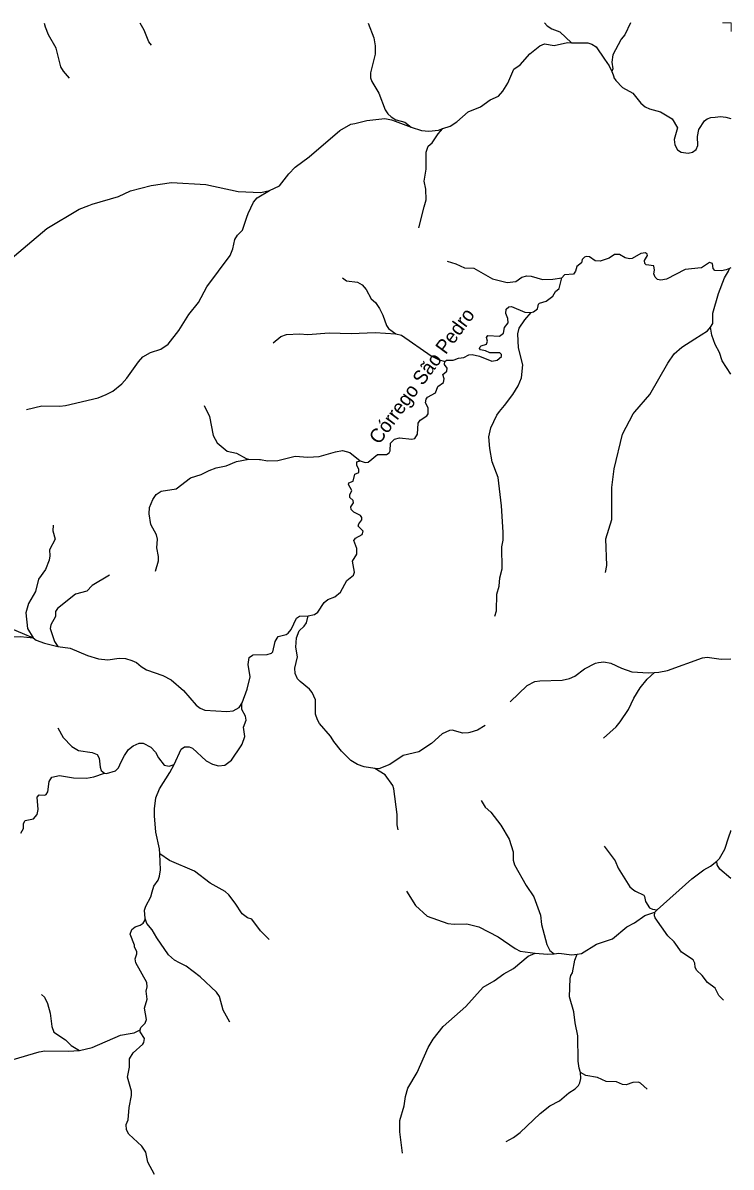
# Model space of a CAD drawing. Extents: x 473.9 to 500, y 7733.1 to 7760.8.
# Drawn here: x 494.97 to 500, y 7752.7 to 7760.82 of the extents above; entities that cross this region are included whole.
import ezdxf
from ezdxf.enums import TextEntityAlignment as Align

# ---------------------------------------------------------------- set-up
doc = ezdxf.new("R2010")
doc.units = 0
doc.header["$LTSCALE"] = 0.032
doc.layers.add('61', color=7, linetype='Continuous')
doc.layers.add('63', color=7, linetype='Continuous', lineweight=13)
doc.layers.add('7', color=7, linetype='Continuous', lineweight=25)

msp = doc.modelspace()

# ---------------------------------------------------------------- linework, layer by layer
at = {"layer": '63'}
msp.add_lwpolyline([(500.0013, 7760.7626), (500.0013, 7760.8242), (499.9406, 7760.8242)], dxfattribs=at)
at = {"layer": '7'}
for p, q in [((500, 7759.0846), (499.9899, 7759.0804)), ((499.4603, 7754.5076), (499.4762, 7754.5246))]:
    msp.add_line(p, q, dxfattribs=at)
for points in [[(495.3045, 7760.4309), (495.2616, 7760.4807), (495.2428, 7760.5119), (495.2083, 7760.6451), (495.1558, 7760.7389), (495.1323, 7760.7939), (495.1263, 7760.8213)], [(495.8869, 7760.6653), (495.8662, 7760.6904), (495.8343, 7760.7738), (495.805, 7760.8218)], [(497.424, 7760.8231), (497.4643, 7760.7172), (497.4745, 7760.6614), (497.4743, 7760.6021), (497.4408, 7760.4688), (497.4415, 7760.4332), (497.4494, 7760.4075), (497.4994, 7760.3251), (497.5462, 7760.2074), (497.5644, 7760.1777), (497.5869, 7760.1563), (497.6212, 7760.1369), (497.6228, 7760.1365), (497.6842, 7760.1198), (497.7308, 7760.0829)], [(498.6761, 7760.824), (498.6951, 7760.8029), (498.728, 7760.7816), (498.7846, 7760.7613), (498.8671, 7760.6826)], [(499.2881, 7760.8245), (499.2471, 7760.7408), (499.2215, 7760.7085), (499.2189, 7760.7052), (499.1624, 7760.5987), (499.155, 7760.5457), (499.1626, 7760.499), (499.1544, 7760.4786)], [(497.9549, 7760.0736), (498.0071, 7760.0907), (498.0539, 7760.1215), (498.134, 7760.1935), (498.2227, 7760.229), (498.2896, 7760.2775), (498.3496, 7760.3029), (498.3806, 7760.3385), (498.416, 7760.3965), (498.4581, 7760.4963), (498.5037, 7760.5276), (498.5726, 7760.6057), (498.6423, 7760.6614), (498.677, 7760.6758), (498.744, 7760.6646), (498.8403, 7760.6854), (498.8671, 7760.6826)], [(498.8671, 7760.6826), (498.9834, 7760.6823), (499.0125, 7760.6741), (499.0441, 7760.6535), (499.1035, 7760.5671), (499.1366, 7760.5191), (499.1544, 7760.4786)], [(499.1544, 7760.4786), (499.1696, 7760.4439), (499.1664, 7760.4399), (499.1823, 7760.4152), (499.2292, 7760.365), (499.3027, 7760.3244), (499.3604, 7760.2548), (499.3912, 7760.2278), (499.4227, 7760.2136), (499.5007, 7760.1926), (499.5819, 7760.1427), (499.6198, 7760.0789), (499.5976, 7759.9954), (499.602, 7759.9571), (499.6205, 7759.9216), (499.6476, 7759.9066), (499.6972, 7759.8981), (499.7261, 7759.9063), (499.7525, 7759.9251), (499.7652, 7759.9537), (499.7619, 7760.0179), (499.7713, 7760.0666), (499.8125, 7760.1282), (499.8305, 7760.1439), (499.8576, 7760.1531), (499.8875, 7760.1559), (499.9253, 7760.1594), (499.9637, 7760.1556), (500, 7760.1457)], [(496.7229, 7759.6338), (496.7959, 7759.6664), (496.8613, 7759.7516), (496.9051, 7759.7986), (497.0058, 7759.8727), (497.2225, 7760.0609), (497.3006, 7760.1039), (497.3294, 7760.1107), (497.416, 7760.1313), (497.5421, 7760.145), (497.5905, 7760.1352), (497.6163, 7760.1256), (497.7308, 7760.0829)], [(497.7308, 7760.0829), (497.8028, 7760.0601), (497.8542, 7760.0548), (497.9231, 7760.0632), (497.9549, 7760.0736)], [(497.7839, 7759.3686), (497.8228, 7759.5174), (497.8362, 7759.5686), (497.8336, 7759.6439), (497.8209, 7759.7011), (497.836, 7759.786), (497.8353, 7759.9072), (497.8514, 7759.9479), (497.8789, 7759.9715), (497.9225, 7760.0373), (497.9549, 7760.0736)], [(494.8378, 7759.1062), (495.1424, 7759.3648), (495.3719, 7759.5015), (495.4409, 7759.5275), (495.4657, 7759.5369), (495.6506, 7759.5914), (495.7372, 7759.6314), (495.884, 7759.6688), (496.0277, 7759.6912), (496.2714, 7759.6768), (496.5005, 7759.6274), (496.6633, 7759.6207), (496.7229, 7759.6338)], [(494.9977, 7758.0788), (495.1072, 7758.1044), (495.2352, 7758.1021), (495.2746, 7758.1078), (495.5078, 7758.1613), (495.5642, 7758.1837), (495.6103, 7758.2077), (495.6751, 7758.2599), (495.7117, 7758.3012), (495.7929, 7758.4178), (495.8254, 7758.452), (495.8795, 7758.4825), (495.9529, 7758.5079), (496.0035, 7758.5418), (496.0795, 7758.6403), (496.1504, 7758.7529), (496.219, 7758.8384), (496.2791, 7758.9498), (496.4439, 7759.1717), (496.4645, 7759.219), (496.4772, 7759.2853), (496.497, 7759.3167), (496.5318, 7759.3526), (496.5623, 7759.4437), (496.5714, 7759.4711), (496.6097, 7759.5501), (496.636, 7759.5815), (496.7229, 7759.6338)], [(497.9842, 7759.1312), (498.0474, 7759.1135), (498.1085, 7759.0836), (498.1748, 7759.0826), (498.3081, 7759.0059), (498.4103, 7758.9801), (498.4727, 7758.988), (498.5165, 7759.0176), (498.5498, 7759.0281), (498.5821, 7759.0258), (498.6616, 7759.0017), (498.7348, 7759.0033), (498.7985, 7759.0127)], [(499.9899, 7759.0804), (499.9663, 7759.0705), (499.934, 7759.0644), (499.8852, 7759.0654), (499.8734, 7759.0799), (499.8698, 7759.116), (499.8472, 7759.1227), (499.7904, 7759.0843), (499.7899, 7759.0842), (499.6758, 7759.0721), (499.5417, 7759.0042), (499.5026, 7758.9969), (499.478, 7759.0019), (499.4616, 7759.0178), (499.4526, 7759.0429), (499.4564, 7759.0684), (499.4519, 7759.0998), (499.3989, 7759.1066), (499.3896, 7759.1145), (499.3874, 7759.1372), (499.4081, 7759.1729), (499.405, 7759.1827), (499.394, 7759.19), (499.3615, 7759.1859), (499.298, 7759.1514), (499.2794, 7759.1486), (499.2498, 7759.1563), (499.2087, 7759.1782), (499.1734, 7759.1804), (499.1362, 7759.1527), (499.0719, 7759.1316), (499.035, 7759.1347), (498.9966, 7759.162), (498.9712, 7759.1645), (498.9594, 7759.1596), (498.9434, 7759.1426), (498.9381, 7759.1208), (498.9052, 7759.0932), (498.8967, 7759.0598), (498.8811, 7759.0405), (498.8182, 7759.0338), (498.7985, 7759.0127)], [(499.855, 7758.6626), (499.8706, 7758.689), (499.8718, 7758.7619), (499.9114, 7758.9017), (499.9533, 7759.0132), (499.9833, 7759.0618), (499.9899, 7759.0804)], [(497.2421, 7759.0136), (497.2702, 7758.9921), (497.3493, 7758.9816), (497.3812, 7758.9647), (497.411, 7758.9295), (497.445, 7758.8638), (497.4762, 7758.8379), (497.5044, 7758.795), (497.5285, 7758.7472), (497.5536, 7758.6756), (497.5689, 7758.6532), (497.6206, 7758.6151)], [(498.581, 7758.7678), (498.5994, 7758.7709), (498.6272, 7758.7934), (498.6308, 7758.8142), (498.6328, 7758.8254), (498.6414, 7758.8344), (498.6883, 7758.8486), (498.7362, 7758.8838), (498.7549, 7758.9167), (498.7813, 7758.937), (498.7985, 7759.0127)], [(497.9691, 7758.4204), (497.9801, 7758.4294), (498.0288, 7758.4294), (498.035, 7758.4317), (498.0649, 7758.4429), (498.1033, 7758.4469), (498.1384, 7758.4676), (498.162, 7758.4701), (498.2143, 7758.4578), (498.3031, 7758.4213), (498.3412, 7758.4282), (498.3709, 7758.4548), (498.3702, 7758.4697), (498.3595, 7758.481), (498.2883, 7758.4807), (498.2581, 7758.4949), (498.222, 7758.5014), (498.2153, 7758.5114), (498.2186, 7758.5246), (498.2259, 7758.5295), (498.2647, 7758.5415), (498.272, 7758.5627), (498.2635, 7758.5887), (498.2744, 7758.6035), (498.3568, 7758.5992), (498.3852, 7758.6208), (498.3932, 7758.6607), (498.4173, 7758.695), (498.4158, 7758.7252), (498.4012, 7758.7591), (498.4031, 7758.7901), (498.4221, 7758.8067), (498.4431, 7758.8107), (498.5361, 7758.7703), (498.581, 7758.7678)], [(498.3226, 7756.6104), (498.3363, 7756.6474), (498.3388, 7756.7658), (498.3546, 7756.823), (498.3596, 7756.8815), (498.3756, 7756.9468), (498.3741, 7757.1038), (498.3836, 7757.1513), (498.3837, 7757.206), (498.3717, 7757.3938), (498.3467, 7757.5964), (498.3059, 7757.7065), (498.2883, 7757.8024), (498.2818, 7757.8832), (498.2953, 7757.947), (498.3374, 7758.0377), (498.3574, 7758.0635), (498.3916, 7758.1076), (498.4511, 7758.1845), (498.4896, 7758.2459), (498.5133, 7758.3043), (498.5215, 7758.395), (498.4927, 7758.5162), (498.4879, 7758.6166), (498.4972, 7758.6555), (498.5369, 7758.7157), (498.581, 7758.7678)], [(496.7492, 7758.5513), (496.8052, 7758.5972), (496.8452, 7758.6104), (496.9372, 7758.616), (496.9956, 7758.6105), (497.1483, 7758.6232), (497.3039, 7758.6177), (497.474, 7758.6257), (497.6206, 7758.6151)], [(499.1083, 7756.9206), (499.118, 7756.9708), (499.1107, 7757.1605), (499.155, 7757.297), (499.155, 7757.5247), (499.171, 7757.6571), (499.2302, 7757.9021), (499.305, 7758.0486), (499.3167, 7758.0621), (499.4237, 7758.1849), (499.552, 7758.4078), (499.5981, 7758.4731), (499.6507, 7758.5219), (499.7447, 7758.5806), (499.8346, 7758.6367), (499.855, 7758.6626)], [(500, 7758.3288), (499.9388, 7758.4243), (499.9184, 7758.4826), (499.8872, 7758.5401), (499.8647, 7758.6057), (499.855, 7758.6626)], [(497.6206, 7758.6151), (497.662, 7758.6063), (497.8724, 7758.4603), (497.9231, 7758.4342), (497.9691, 7758.4204)], [(497.3677, 7757.714), (497.4031, 7757.7025), (497.425, 7757.7041), (497.4897, 7757.7585), (497.5535, 7757.7589), (497.5735, 7757.7708), (497.5806, 7757.7845), (497.5834, 7757.838), (497.6108, 7757.8687), (497.6479, 7757.8759), (497.7337, 7757.868), (497.7569, 7757.8731), (497.7735, 7757.903), (497.7805, 7757.9823), (497.7931, 7758.0021), (497.84, 7758.0331), (497.8513, 7758.0479), (497.8504, 7758.0897), (497.8321, 7758.125), (497.8362, 7758.1512), (497.8453, 7758.1648), (497.9026, 7758.1971), (497.9188, 7758.2407), (497.9587, 7758.2708), (497.9633, 7758.2965), (497.9556, 7758.3273), (497.9828, 7758.3503), (497.9857, 7758.3715), (497.9657, 7758.3991), (497.9691, 7758.4204)], [(496.261, 7758.1078), (496.2978, 7758.0296), (496.3247, 7757.8934), (496.3533, 7757.841), (496.4242, 7757.783), (496.4892, 7757.768), (496.5582, 7757.7296), (496.5772, 7757.7265)], [(496.5772, 7757.7265), (496.6536, 7757.7236), (496.6591, 7757.7227), (496.7105, 7757.7141), (496.7821, 7757.7155), (496.9067, 7757.7461), (496.9954, 7757.7397), (497.0755, 7757.7437), (497.1924, 7757.7782), (497.241, 7757.7861), (497.2932, 7757.7717), (497.3677, 7757.714)], [(495.9145, 7756.93), (495.9365, 7757.0038), (495.9365, 7757.0349), (495.923, 7757.0947), (495.9285, 7757.1568), (495.9221, 7757.1869), (495.8809, 7757.261), (495.8692, 7757.3372), (495.8725, 7757.381), (495.8958, 7757.439), (495.9203, 7757.4749), (495.9545, 7757.4992), (496.0606, 7757.5154), (496.163, 7757.5923), (496.239, 7757.6176), (496.2958, 7757.645), (496.3442, 7757.6628), (496.4155, 7757.6791), (496.4905, 7757.7094), (496.5772, 7757.7265)], [(496.9994, 7756.6134), (497.0427, 7756.6227), (497.066, 7756.6394), (497.1118, 7756.7066), (497.1375, 7756.7281), (497.1875, 7756.7475), (497.228, 7756.7813), (497.2728, 7756.8644), (497.3205, 7756.9021), (497.3276, 7756.9227), (497.3141, 7757.0001), (497.3445, 7757.0497), (497.3431, 7757.0912), (497.3221, 7757.1468), (497.3289, 7757.1561), (497.3341, 7757.1632), (497.3816, 7757.1915), (497.3894, 7757.2142), (497.3542, 7757.2486), (497.3591, 7757.2673), (497.3789, 7757.2952), (497.3805, 7757.3115), (497.3704, 7757.3262), (497.3226, 7757.3481), (497.3035, 7757.3689), (497.3022, 7757.3864), (497.321, 7757.4156), (497.3171, 7757.4309), (497.2946, 7757.4536), (497.2933, 7757.4723), (497.3083, 7757.5022), (497.2836, 7757.5464), (497.2876, 7757.5575), (497.3187, 7757.5699), (497.3288, 7757.6185), (497.3572, 7757.6308), (497.3581, 7757.6545), (497.343, 7757.6799), (497.3445, 7757.7073), (497.3677, 7757.714)], [(493.5277, 7757.5933), (493.561, 7757.4945), (493.5804, 7757.4738), (493.6057, 7757.4629), (493.6698, 7757.4565), (493.7198, 7757.4394), (493.7579, 7757.4112), (493.8247, 7757.3032), (493.8904, 7757.2251), (494.0045, 7757.126), (494.0454, 7757.097), (494.1642, 7757.0356), (494.2971, 7756.9448), (494.3878, 7756.8727), (494.468, 7756.7805), (494.5012, 7756.756), (494.5515, 7756.7299), (494.7189, 7756.6664), (494.7582, 7756.645), (494.7736, 7756.632), (494.7854, 7756.6081), (494.8159, 7756.5705), (494.8609, 7756.5353), (495.0451, 7756.4561)], [(495.1876, 7757.2561), (495.1866, 7757.2156), (495.2013, 7757.1577), (495.1622, 7757.0821), (495.1652, 7757.039), (495.1596, 7757.007), (495.1337, 7756.9413), (495.0827, 7756.8728), (495.0629, 7756.7854), (495.0118, 7756.7007), (494.9938, 7756.6344), (495.0047, 7756.5224), (495.0451, 7756.4561)], [(495.5871, 7756.902), (495.4654, 7756.829), (495.428, 7756.7887), (495.3471, 7756.7665), (495.2186, 7756.6656), (495.2039, 7756.6446), (495.2036, 7756.609), (495.1723, 7756.5484), (495.1668, 7756.5234), (495.1975, 7756.4301), (495.2218, 7756.3953)], [(496.5297, 7755.994), (496.5649, 7756.0913), (496.5873, 7756.1797), (496.5717, 7756.2681), (496.5796, 7756.3162), (496.6033, 7756.3325), (496.6073, 7756.3353), (496.7083, 7756.3374), (496.7378, 7756.3464), (496.7485, 7756.358), (496.7637, 7756.4306), (496.7848, 7756.4648), (496.8418, 7756.479), (496.8575, 7756.4887), (496.8774, 7756.5152), (496.9159, 7756.5959), (496.9364, 7756.61), (496.9994, 7756.6134)], [(497.4728, 7755.5279), (497.3955, 7755.5396), (497.3486, 7755.5556), (497.3022, 7755.5841), (497.2352, 7755.6504), (497.1798, 7755.7194), (497.161, 7755.7503), (497.1559, 7755.7587), (497.0786, 7755.847), (497.0644, 7755.8743), (497.0511, 7755.9137), (497.051, 7756.017), (497.0274, 7756.0685), (497.0087, 7756.0918), (496.941, 7756.1452), (496.9235, 7756.1654), (496.9072, 7756.2022), (496.9045, 7756.2407), (496.9235, 7756.3206), (496.91, 7756.3899), (496.9157, 7756.4567), (496.9355, 7756.507), (496.9707, 7756.5392), (496.9866, 7756.5628), (496.9994, 7756.6134)], [(494.2915, 7756.2975), (494.3194, 7756.2933), (494.399, 7756.2973), (494.5887, 7756.3391), (494.6419, 7756.3556), (494.7282, 7756.3955), (494.8372, 7756.4459), (494.9032, 7756.4639), (494.9549, 7756.4649), (495.0451, 7756.4561)], [(495.0451, 7756.4561), (495.0667, 7756.4397), (495.1273, 7756.4184), (495.2218, 7756.3953)], [(495.2218, 7756.3953), (495.3093, 7756.3839), (495.4317, 7756.3316), (495.5089, 7756.3073), (495.5748, 7756.3012), (495.6566, 7756.3117), (495.7008, 7756.3085), (495.7475, 7756.2957), (495.7788, 7756.2808), (495.8118, 7756.2524), (495.8501, 7756.2298), (495.9673, 7756.1889), (496.0251, 7756.1583), (496.1135, 7756.0827), (496.2024, 7755.9785), (496.231, 7755.9569), (496.2642, 7755.9432), (496.4213, 7755.9325), (496.4647, 7755.937), (496.508, 7755.9627), (496.5297, 7755.994)], [(498.4326, 7756.0022), (498.5537, 7756.1172), (498.6071, 7756.1452), (498.6431, 7756.1521), (498.801, 7756.1565), (498.8541, 7756.1683), (498.8922, 7756.1844), (498.9614, 7756.2364), (499.0389, 7756.2769), (499.059, 7756.2821), (499.0979, 7756.2868), (499.1466, 7756.2773), (499.2226, 7756.2418), (499.2971, 7756.2153), (499.4158, 7756.2075), (499.4585, 7756.2104)], [(499.4585, 7756.2104), (499.4875, 7756.2123), (499.5489, 7756.2248), (499.7983, 7756.315), (499.8316, 7756.3189), (499.9319, 7756.3037), (500, 7756.3083)], [(499.0944, 7755.7434), (499.1846, 7755.8234), (499.2148, 7755.8589), (499.2736, 7755.9462), (499.3106, 7756.0281), (499.3563, 7756.1003), (499.4057, 7756.1631), (499.4585, 7756.2104)], [(496.0462, 7755.5577), (496.0968, 7755.6651), (496.1215, 7755.6824), (496.1543, 7755.6823), (496.1771, 7755.6718), (496.2747, 7755.5831), (496.3198, 7755.5596), (496.361, 7755.5466), (496.4061, 7755.5531), (496.4544, 7755.5875), (496.5229, 7755.6902), (496.5301, 7755.701), (496.549, 7755.7545), (496.5404, 7755.8218), (496.5578, 7755.8715), (496.5538, 7755.8999), (496.5284, 7755.9478), (496.5279, 7755.9891), (496.5297, 7755.994)], [(495.2199, 7755.816), (495.2584, 7755.7496), (495.3195, 7755.6856), (495.3673, 7755.6571), (495.4654, 7755.6422), (495.4998, 7755.6275), (495.5148, 7755.6018), (495.5211, 7755.5366), (495.5295, 7755.5146), (495.5516, 7755.4942)], [(498.2554, 7755.8347), (498.2006, 7755.8008), (498.1473, 7755.7843), (498.1366, 7755.781), (498.096, 7755.7794), (498.0199, 7755.8001), (498.0007, 7755.7986), (497.9509, 7755.7734), (497.8732, 7755.7057), (497.7834, 7755.6476), (497.673, 7755.6212), (497.5792, 7755.5559), (497.499, 7755.5268), (497.4728, 7755.5279)], [(495.5516, 7755.4942), (495.5657, 7755.4935), (495.6301, 7755.512), (495.651, 7755.5329), (495.6717, 7755.5745), (495.6948, 7755.6212), (495.7231, 7755.6628), (495.7548, 7755.6891), (495.7979, 7755.7079), (495.826, 7755.7087), (495.8815, 7755.6797), (495.9145, 7755.6447), (495.9357, 7755.6033), (495.977, 7755.5508), (496.0116, 7755.5453), (496.0462, 7755.5577)], [(495.9441, 7754.9231), (495.9425, 7754.9573), (495.9158, 7755.075), (495.9062, 7755.1921), (495.9063, 7755.2428), (495.917, 7755.3194), (495.9434, 7755.3839), (496.0161, 7755.499), (496.0462, 7755.5577)], [(494.9575, 7755.0697), (494.978, 7755.103), (494.9761, 7755.1365), (494.9902, 7755.1591), (495.0491, 7755.1713), (495.075, 7755.2014), (495.0803, 7755.2363), (495.0731, 7755.3255), (495.0879, 7755.3422), (495.1277, 7755.3392), (495.1381, 7755.344), (495.1493, 7755.3615), (495.1591, 7755.4352), (495.1779, 7755.4675), (495.233, 7755.4786), (495.3333, 7755.4612), (495.4247, 7755.4602), (495.4767, 7755.4683), (495.5516, 7755.4942)], [(497.6383, 7755.092), (497.63, 7755.1272), (497.6307, 7755.2025), (497.6075, 7755.3837), (497.599, 7755.4079), (497.5452, 7755.4824), (497.4728, 7755.5279)], [(498.2277, 7755.3021), (498.2553, 7755.254), (498.2952, 7755.2183), (498.3657, 7755.1269), (498.4261, 7755.0264), (498.4531, 7754.9354), (498.455, 7754.8778), (498.4636, 7754.8451), (498.5461, 7754.6976), (498.6012, 7754.6161), (498.6483, 7754.4865), (498.6548, 7754.419), (498.6918, 7754.2778), (498.7146, 7754.2354), (498.7458, 7754.2128)], [(499.8998, 7754.8711), (499.9196, 7754.8901), (499.9569, 7754.9555), (499.9856, 7755.0432), (499.9985, 7755.0826), (500, 7755.0872)], [(499.1006, 7754.9758), (499.1788, 7754.872), (499.2001, 7754.8209), (499.2827, 7754.6879), (499.3107, 7754.6633), (499.3233, 7754.6569), (499.3809, 7754.6279), (499.3875, 7754.6192), (499.3935, 7754.5831), (499.4226, 7754.5392), (499.4423, 7754.5293), (499.4762, 7754.5246)], [(495.84, 7754.4621), (495.8372, 7754.5208), (495.8447, 7754.5513), (495.8811, 7754.6164), (495.8919, 7754.6526), (495.9036, 7754.6918), (495.9328, 7754.7362), (495.9422, 7754.7642), (495.9494, 7754.8088), (495.9441, 7754.9231)], [(496.7209, 7754.3132), (496.6593, 7754.3752), (496.5979, 7754.457), (496.567, 7754.4683), (496.5286, 7754.4954), (496.4807, 7754.5707), (496.4343, 7754.6314), (496.4094, 7754.6546), (496.3032, 7754.7133), (496.192, 7754.7989), (496.0138, 7754.874), (495.9441, 7754.9231)], [(499.4762, 7754.5246), (499.7232, 7754.7448), (499.8087, 7754.8093), (499.8551, 7754.834), (499.8998, 7754.8711)], [(500, 7754.7469), (499.9212, 7754.8126), (499.903, 7754.844), (499.8998, 7754.8711)], [(497.6964, 7754.6581), (497.7598, 7754.5552), (497.8427, 7754.4787), (497.9902, 7754.4281), (498.0361, 7754.422), (498.1238, 7754.4243), (498.2094, 7754.403), (498.3477, 7754.3324), (498.4692, 7754.2489), (498.5042, 7754.2309), (498.6107, 7754.216)], [(498.9084, 7754.2101), (498.9401, 7754.2147), (499.0462, 7754.281), (499.1584, 7754.3186), (499.2598, 7754.4036), (499.3156, 7754.4325), (499.3893, 7754.483), (499.4603, 7754.5076)], [(499.9468, 7753.8819), (499.9151, 7753.915), (499.8877, 7753.9688), (499.833, 7754.0084), (499.7961, 7754.0574), (499.7566, 7754.0946), (499.7451, 7754.1162), (499.7433, 7754.1456), (499.7323, 7754.1699), (499.6483, 7754.2236), (499.5966, 7754.2976), (499.553, 7754.3398), (499.4632, 7754.467), (499.4581, 7754.4822), (499.4603, 7754.5076)], [(495.8051, 7753.6711), (495.811, 7753.6889), (495.8422, 7753.7186), (495.8499, 7753.7453), (495.8355, 7753.8265), (495.8557, 7753.89), (495.8485, 7753.9477), (495.8556, 7753.9762), (495.8532, 7754.007), (495.7752, 7754.1476), (495.7691, 7754.1774), (495.7809, 7754.2109), (495.781, 7754.2291), (495.7654, 7754.2585), (495.7649, 7754.2743), (495.7338, 7754.3523), (495.7466, 7754.3851), (495.7699, 7754.4026), (495.806, 7754.4144), (495.8277, 7754.4301), (495.8395, 7754.4497), (495.84, 7754.4621)], [(496.4428, 7753.7259), (496.3943, 7753.812), (496.3679, 7753.9079), (496.3468, 7753.9394), (496.2327, 7754.0488), (496.1311, 7754.123), (496.0858, 7754.1482), (496.0502, 7754.1679), (496.0077, 7754.2049), (495.9229, 7754.3249), (495.8898, 7754.3829), (495.8529, 7754.4284), (495.84, 7754.4621)], [(497.6675, 7752.7961), (497.6493, 7752.9467), (497.6501, 7753.0271), (497.6796, 7753.1319), (497.6893, 7753.1995), (497.7071, 7753.2572), (497.7712, 7753.3678), (497.8511, 7753.5454), (497.8865, 7753.6057), (497.9568, 7753.6961), (498.119, 7753.8374), (498.2419, 7753.9741), (498.3194, 7754.0196), (498.3874, 7754.0701), (498.4556, 7754.108), (498.5609, 7754.1948), (498.6107, 7754.216)], [(498.6107, 7754.216), (498.6984, 7754.2087), (498.7458, 7754.2128)], [(498.7458, 7754.2128), (498.7791, 7754.2156), (498.8704, 7754.2046), (498.9084, 7754.2101)], [(498.9321, 7753.3697), (498.922, 7753.4007), (498.9161, 7753.45), (498.9137, 7753.6302), (498.8932, 7753.7221), (498.8856, 7753.8002), (498.8535, 7753.9052), (498.8583, 7754.0366), (498.863, 7754.0584), (498.8743, 7754.0761), (498.8919, 7754.1658), (498.9084, 7754.2101)], [(495.1039, 7753.9238), (495.1269, 7753.9044), (495.1474, 7753.8589), (495.1669, 7753.7903), (495.1778, 7753.6963), (495.1924, 7753.6565), (495.2764, 7753.601), (495.3147, 7753.5606), (495.3752, 7753.5255)], [(495.3752, 7753.5255), (495.4658, 7753.5466), (495.666, 7753.6349), (495.7348, 7753.6453), (495.7626, 7753.6495), (495.8051, 7753.6711)], [(495.9073, 7752.6441), (495.8604, 7752.733), (495.8452, 7752.8028), (495.8185, 7752.8459), (495.7255, 7752.9317), (495.7081, 7752.9627), (495.7073, 7753.0002), (495.7207, 7753.0317), (495.7275, 7753.1203), (495.7441, 7753.2053), (495.7432, 7753.2352), (495.7162, 7753.3352), (495.7297, 7753.4073), (495.7306, 7753.4653), (495.7567, 7753.5076), (495.8254, 7753.5691), (495.8323, 7753.5828), (495.8354, 7753.6113), (495.805, 7753.6569), (495.8051, 7753.6711)], [(494.2408, 7753.2987), (494.3648, 7753.3234), (494.4938, 7753.3267), (494.6085, 7753.3411), (494.7107, 7753.3722), (494.8016, 7753.3837), (494.8507, 7753.4074), (494.9043, 7753.4605), (495.0892, 7753.5165), (495.1277, 7753.5223), (495.2944, 7753.52), (495.3752, 7753.5255)], [(498.4031, 7752.8786), (498.456, 7752.907), (498.5029, 7752.9425), (498.6457, 7753.078), (498.7144, 7753.1321), (498.7829, 7753.1672), (498.8492, 7753.2247), (498.8948, 7753.2517), (498.9186, 7753.2772), (498.9278, 7753.2964), (498.9344, 7753.3258), (498.9321, 7753.3697)], [(499.4061, 7753.2506), (499.3581, 7753.2936), (499.3429, 7753.2993), (499.3037, 7753.2986), (499.2556, 7753.282), (499.2301, 7753.2843), (499.1886, 7753.3026), (499.1143, 7753.3056), (499.0533, 7753.3324), (498.9699, 7753.3478), (498.9321, 7753.3697)]]:
    msp.add_lwpolyline(points, dxfattribs=at)

# ---------------------------------------------------------------- texts
at = {"layer": '61'}
msp.add_text('Córrego São Pedro', height=0.1, rotation=53.577, dxfattribs=at).set_placement((497.8445, 7758.2875), align=Align.CENTER)

doc.saveas('drawing.dxf')
